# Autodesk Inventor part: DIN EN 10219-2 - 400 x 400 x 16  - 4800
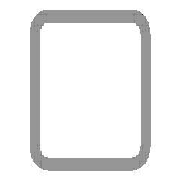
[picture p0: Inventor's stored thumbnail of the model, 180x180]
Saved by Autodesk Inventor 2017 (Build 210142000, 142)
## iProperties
IsCustomPart: 1
Created: 2017-11
Part Number: DIN EN 10219-2 - 400 x 400 x 16  - 4800
Material: Steel, Mild
Description: Cold formed welded structural hollow sections of non-alloy and fine grain structural steel
Document SubType Name: Modeling
Standard: DIN
Designer: iusti
Standard Revision: 2006-07
Standards Organization: DIN
Language: en-US
Size Designation: 400 x 400 x 16
Categories: <MemberInstance><Categories><Category DisplayName="Structural Shapes" InternalName="089c4875-fa83-4c05-b084-43b9cc11f5ed" Mnemonic="GRDR"><CategoryParameter Dis
Stock Number: 400 x 400 x 16
Density: 7.85 g/cm^3
Appearance: Semi-Polished
Mass: 884622 g
Surface Area: 141333 cm^2
Volume: 112691 cm^3
_CCFamilyMember: 142
_CCFamilyDisplayName: DIN EN 10219-2 (Square Hollow Section - Cold Formed) - Cold formed welded structural hollow sections of non-alloy and fine grain structural steel
_FrameMemberDoc: Frame Member File
_Version: 15.0.0
_GetPNFromCC: 1
G_L: 4800.000 mm
G_W: 400.000 mm
G_H: 400.000 mm
+07E149D3-E7B6-449F-B06C-092C84D7F120+CUTDETAIL1: Cut
Author: iusti
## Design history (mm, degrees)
node "Start plane"
node "End plane"
sketch "Sketch"
  geometry: L1 (-200, -152)-(-200, 152); L2 (-152, 200)-(152, 200); L3 (200, 152)-(200, -152); L4 (152, -200)-(-152, -200); L5 (-152, 184)-(152, 184); L6 (184, 152)-(184, -152); L7 (152, -184)-(-152, -184); L8 (-184, -152)-(-184, 152); L9 (0, 293.918)-(0, -293.918) reference; L10 (-293.918, 0)-(293.918, 0) reference; A1 r 48 centre (-152, -152) between (-200, -152) and (-152, -200); A2 r 48 centre (-152, 152) between (-152, 200) and (-200, 152); A3 r 48 centre (152, 152) between (200, 152) and (152, 200); A4 r 48 centre (152, -152) between (152, -200) and (200, -152); A5 r 32 centre (-152, 152) between (-152, 184) and (-184, 152); A6 r 32 centre (152, 152) between (184, 152) and (152, 184); A7 r 32 centre (152, -152) between (152, -184) and (184, -152); A8 r 32 centre (-152, -152) between (-184, -152) and (-152, -184)
  constraints: 16 end point, 16 point on circle, 8 centre point, 8 tangent, 4 parallel, 3 equal radius, 2 perpendicular, 7 other
  dimensions: "d7" = 48 radius of A1 (= G_IR); "d10" = 400 distance between parallel lines of L2 L4 (= G_H); "d11" = 400 distance between parallel lines of L1 L3 (= G_W); "d12" = 16 distance between parallel lines of L3 L6 (= G_T); "d15" = 200 distance between parallel lines of L2 L10 (= 0.5 x d10); "d16" = 200 distance between parallel lines of L9 L3 (= 0.5 x d11)
extrude "Body" new body sketch "Sketch" stored distance "d3" = 4800 (= G_L); taper "d4" = 0 deg
node "Driven Length"
  sketch "Sketch3"
    geometry: L1 (0, 0)-(10, 0) reference
    constraints: 2 end point, 1 horizontal
  workplane "Work Plane3"
  sketch "Sketch4"
    geometry: L1 (-2, 200)-(12, 200) reference; L2 (-2, 5000)-(12, 5000) reference
    dimensions: "d18" = 4800 distance between parallel lines of L1 L2 (derived)
workplane "Work Plane4"
split "Split1"
body "Solid1"
other parameters: "G_W" = 400 [user parameter; used in 1 equation term], "G_H" = 400 [user parameter; used in 1 equation term], "G_T" = 16 [user parameter; used in 1 equation term], "G_IR" = 48 [user parameter; used in 1 equation term], "G_L" = 4800 (= d18) [user parameter; used in 1 equation term], "G_OFFSET_END" = 0 [user parameter; used in 1 equation term], "d17" = 90 deg
